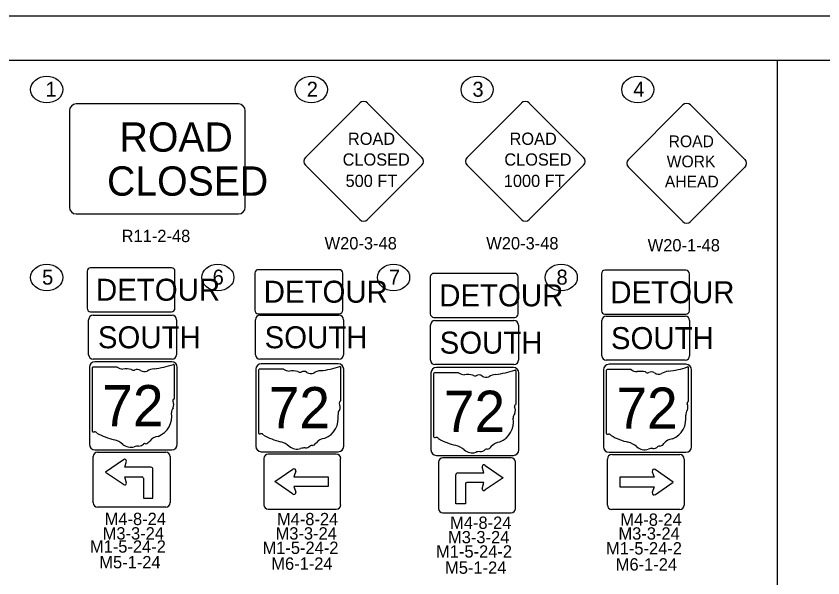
# Model space of a CAD drawing. Extents: x 0 to 784, y 0 to 440.
# Drawn here: x 466.8 to 650.3, y 312.3 to 440 of the extents above; entities that cross this region are included whole.
import ezdxf

# ---------------------------------------------------------------- set-up
doc = ezdxf.new("R2010")
doc.units = 0
for name, color, linetype in [('Default', 7, 'Continuous'), ('SH_Border', 7, 'Continuous'), ('SH_Cut_Line', 7, 'Continuous'), ('SN_P_Signs', 7, 'Continuous'), ('SN_P_Text', 7, 'Continuous'), ('SN_X_Public', 7, 'Continuous')]:
    doc.layers.add(name, color=color, linetype=linetype)

msp = doc.modelspace()

# ---------------------------------------------------------------- linework, layer by layer
at = {"layer": 'Default'}
for centre in [(473.78, 423.3), (533.97, 423.3), (571.68, 423.3), (608.24, 423.3), (473.78, 380.58), (512.71, 380.58), (552.68, 380.58), (590.82, 380.58)]:
    msp.add_ellipse(centre, major_axis=(3.66, 0), ratio=0.82844, dxfattribs=at)
at = {"layer": 'SH_Border'}
msp.add_line((640, 10), (640, 430), dxfattribs=at)
msp.add_lwpolyline([(30, 430), (670, 430), (670, 10), (30, 10)], close=True, dxfattribs=at)
at = {"layer": 'SH_Cut_Line'}
msp.add_lwpolyline([(0, 0), (680, 0), (680, 440), (0, 440)], close=True, dxfattribs=at)
at = {"layer": 'SN_P_Signs'}
for p, q in [((483.32, 362.99), (483.32, 370.99)), ((484.32, 371.99), (502.32, 371.99)), ((503.32, 370.99), (503.32, 362.99)), ((521.26, 362.99), (521.26, 370.99)), ((522.26, 371.99), (540.26, 371.99)), ((541.26, 370.99), (541.26, 362.99)), ((562.07, 370.77), (580.07, 370.77)), ((600.03, 362.8), (600.03, 370.8)), ((601.03, 371.8), (619.03, 371.8)), ((620.03, 370.8), (620.03, 362.8)), ((561.07, 361.77), (561.07, 369.77)), ((581.07, 369.77), (581.07, 361.77)), ((502.32, 361.99), (484.32, 361.99)), ((540.26, 361.99), (522.26, 361.99)), ((619.03, 361.8), (601.03, 361.8)), ((484.09, 359.97), (484.09, 345.74)), ((489.77, 360.22), (484.28, 360.22)), ((502.84, 353.13), (502.84, 360.57)), ((527.63, 359.77), (522.14, 359.77)), ((540.7, 352.68), (540.7, 360.13)), ((580.07, 360.77), (562.07, 360.77)), ((619.8, 352.56), (619.8, 360)), ((521.95, 359.53), (521.95, 345.3)), ((561.79, 358.7), (561.79, 344.47)), ((567.47, 358.94), (561.98, 358.94)), ((580.54, 351.85), (580.54, 359.29)), ((601.05, 359.4), (601.05, 345.17)), ((606.72, 359.65), (601.23, 359.65)), ((502.84, 353.13), (502.84, 353.13)), ((540.7, 352.68), (540.7, 352.68)), ((619.8, 352.56), (619.8, 352.56)), ((580.54, 351.85), (580.54, 351.85)), ((484.35, 329.38), (484.35, 339.88)), ((485.35, 340.88), (500.85, 340.88)), ((501.85, 339.88), (501.85, 329.38)), ((539.64, 340.43), (524.14, 340.43)), ((539.65, 340.43), (539.64, 340.43)), ((579.42, 339.6), (563.92, 339.6)), ((602.31, 340.31), (617.81, 340.31)), ((491.24, 339.15), (487.16, 336.35)), ((491.54, 337.45), (491.95, 338.85)), ((523.14, 339.43), (523.14, 328.93)), ((540.64, 328.93), (540.64, 339.43)), ((562.92, 338.6), (562.92, 328.1)), ((573.53, 337.86), (577.61, 335.07)), ((580.42, 328.1), (580.42, 338.6)), ((601.31, 328.81), (601.31, 339.31)), ((618.81, 339.31), (618.81, 328.81)), ((487.16, 336.35), (491.24, 333.56)), ((497.48, 337.45), (491.54, 337.45)), ((497.48, 337.45), (497.48, 337.45)), ((497.94, 330.41), (497.94, 336.98)), ((525.64, 334.18), (529.78, 337.03)), ((530.42, 336.56), (530.02, 335.28)), ((567.29, 336.16), (573.23, 336.16)), ((567.29, 336.16), (567.29, 336.16)), ((573.23, 336.16), (572.81, 337.57)), ((611.54, 336.43), (611.94, 335.15)), ((616.31, 334.06), (612.17, 336.9)), ((491.95, 333.85), (491.54, 335.26)), ((491.54, 335.26), (495.44, 335.26)), ((495.76, 334.95), (495.76, 330.41)), ((529.72, 331.39), (525.64, 334.18)), ((530.02, 335.28), (537.83, 335.28)), ((537.83, 335.28), (537.83, 333.09)), ((566.82, 329.13), (566.82, 335.69)), ((577.61, 335.07), (573.53, 332.27)), ((611.94, 335.15), (604.12, 335.15)), ((604.12, 335.15), (604.12, 332.96)), ((612.23, 331.26), (616.31, 334.06)), ((537.83, 333.09), (530.02, 333.09)), ((530.02, 333.09), (530.42, 331.81)), ((569.01, 333.66), (569.01, 329.13)), ((573.23, 333.97), (569.32, 333.97)), ((572.81, 332.57), (573.23, 333.97)), ((604.12, 332.96), (611.94, 332.96)), ((611.94, 332.96), (611.54, 331.68)), ((495.76, 330.41), (497.94, 330.41)), ((495.76, 330.41), (497.94, 330.41)), ((569.01, 329.13), (566.82, 329.13)), ((500.85, 328.38), (485.35, 328.38)), ((524.14, 327.93), (539.64, 327.93)), ((563.92, 327.1), (579.42, 327.1)), ((617.81, 327.81), (602.31, 327.81))]:
    msp.add_line(p, q, dxfattribs=at)
for points in [[(532.61, 407.88), (544.99, 420.25)], [(546.75, 420.25), (559.13, 407.88)], [(569.39, 407.88), (581.76, 420.25)], [(583.53, 420.25), (595.91, 407.88)], [(478.94, 418.46), (478.94, 396.6)], [(517.37, 420.03), (480.5, 420.03)], [(518.94, 396.6), (518.94, 418.46)], [(606.11, 407.43), (618.48, 419.8)], [(620.25, 419.8), (632.62, 407.43)], [(544.99, 393.73), (532.61, 406.11)], [(559.13, 406.11), (546.75, 393.73)], [(581.76, 393.73), (569.39, 406.11)], [(595.91, 406.11), (583.53, 393.73)], [(618.48, 393.28), (606.11, 405.66)], [(632.62, 405.66), (620.25, 393.28)], [(480.5, 395.03), (517.37, 395.03)], [(482.96, 382), (482.96, 373.6)], [(502.16, 382.8), (483.76, 382.8)], [(502.96, 373.6), (502.96, 382)], [(483.76, 372.8), (502.16, 372.8)], [(483.48, 360.16), (483.48, 342.66)], [(502.23, 361.41), (484.73, 361.41)], [(503.48, 342.66), (503.48, 360.16)], [(521.34, 359.72), (521.34, 342.22)], [(540.09, 360.97), (522.59, 360.97)], [(541.34, 342.22), (541.34, 359.72)], [(579.93, 360.14), (562.43, 360.14)], [(619.19, 360.84), (601.69, 360.84)], [(561.18, 358.89), (561.18, 341.39)], [(581.18, 341.39), (581.18, 358.89)], [(600.44, 359.59), (600.44, 342.09)], [(620.44, 342.09), (620.44, 359.59)], [(484.73, 341.41), (502.23, 341.41)], [(522.59, 340.97), (540.09, 340.97)], [(562.43, 340.14), (579.93, 340.14)], [(601.69, 340.84), (619.19, 340.84)]]:
    msp.add_lwpolyline(points, dxfattribs=at)
for centre, radius, start, end in [((545.87, 419.37), 1.25, 45, 135), ((582.65, 419.37), 1.25, 45, 135), ((480.5, 418.46), 1.57, 90, 180), ((517.37, 418.46), 1.57, 0, 90), ((619.36, 418.92), 1.25, 45, 135), ((533.5, 406.99), 1.25, 135, 225), ((558.24, 406.99), 1.25, 315, 45), ((570.27, 406.99), 1.25, 135, 225), ((595.02, 406.99), 1.25, 315, 45), ((606.99, 406.54), 1.25, 135, 225), ((631.74, 406.54), 1.25, 315, 45), ((480.5, 396.6), 1.57, 180, 270), ((517.37, 396.6), 1.57, 270, 0), ((545.87, 394.62), 1.25, 225, 315), ((582.65, 394.62), 1.25, 225, 315), ((619.36, 394.17), 1.25, 225, 315), ((483.76, 382), 0.8, 90, 180), ((502.16, 382), 0.8, 0, 90), ((483.76, 373.6), 0.8, 180, 270), ((502.16, 373.6), 0.8, 270, 0), ((484.32, 370.99), 1, 90, 180), ((502.32, 370.99), 1, 0, 90), ((522.26, 370.99), 1, 90, 180), ((540.26, 370.99), 1, 0, 90), ((562.07, 369.77), 1, 90, 180), ((580.07, 369.77), 1, 0, 90), ((601.03, 370.79), 1, 90, 180), ((619.03, 370.79), 1, 0, 90), ((484.32, 362.99), 1, 180, 270), ((502.32, 362.99), 1, 270, 0), ((522.26, 362.99), 1, 180, 270), ((540.26, 362.99), 1, 270, 0), ((562.07, 361.77), 1, 180, 270), ((580.07, 361.77), 1, 270, 0), ((601.03, 362.79), 1, 180, 270), ((619.03, 362.79), 1, 270, 0), ((484.73, 360.16), 1.25, 90, 180), ((484.31, 360), 0.217, 98.1301, 188.1301), ((491.08, 361.87), 2.11, 231.6195, 271.1119), ((491.78, 352.23), 7.56, 80.4867, 94.9883), ((493.49, 360.08), 0.608, 219.7921, 297.1024), ((494.38, 358.43), 1.26, 54.4667, 119.1411), ((498.7, 355.87), 4, 97.3462, 120.7689), ((496.16, 379.62), 19.88, 275.8445, 288.9065), ((502.23, 360.16), 1.25, 0, 90), ((502.63, 360.6), 0.209, 351.8621, 97.738), ((522.59, 359.72), 1.25, 90, 180), ((522.17, 359.56), 0.217, 98.1301, 188.1301), ((528.94, 361.43), 2.11, 231.6195, 271.1119), ((534.02, 379.18), 19.88, 275.8445, 288.9065), ((540.09, 359.72), 1.25, 0, 90), ((540.49, 360.16), 0.209, 351.8621, 97.738), ((562.43, 358.89), 1.25, 90, 180), ((579.93, 358.89), 1.25, 0, 90), ((601.69, 359.59), 1.25, 90, 180), ((613.12, 379.05), 19.88, 275.8445, 288.9065), ((619.19, 359.59), 1.25, 0, 90), ((619.59, 360.03), 0.209, 351.8621, 97.738), ((496.02, 360.69), 1.52, 233.8562, 294.8282), ((529.63, 351.78), 7.56, 80.4867, 94.9883), ((531.35, 359.63), 0.608, 219.7921, 297.1024), ((532.24, 357.99), 1.26, 54.4667, 119.1411), ((533.88, 360.24), 1.52, 233.8562, 294.8282), ((536.56, 355.43), 4, 97.3462, 120.7689), ((562.01, 358.73), 0.217, 98.1301, 188.1301), ((568.77, 360.59), 2.11, 231.6195, 271.1119), ((569.47, 350.95), 7.56, 80.4867, 94.9883), ((571.19, 358.8), 0.608, 219.7921, 297.1024), ((572.08, 357.16), 1.26, 54.4667, 119.1411), ((573.71, 359.41), 1.52, 233.8562, 294.8282), ((576.4, 354.59), 4, 97.3462, 120.7689), ((573.86, 378.34), 19.88, 275.8445, 288.9065), ((580.33, 359.32), 0.209, 351.8621, 97.738), ((601.26, 359.43), 0.217, 98.1301, 188.1301), ((608.03, 361.3), 2.11, 231.6195, 271.1119), ((608.73, 351.66), 7.56, 80.4867, 94.9883), ((610.45, 359.51), 0.608, 219.7921, 297.1024), ((611.34, 357.86), 1.26, 54.4667, 119.1411), ((612.97, 360.12), 1.52, 233.8562, 294.8282), ((615.66, 355.3), 4, 97.3462, 120.7689), ((502.79, 352.58), 0.323, 107.944, 210.337), ((500.74, 351.64), 1.94, 340.033, 23.6496), ((502.62, 353.1), 0.223, 289.6038, 7.7341), ((540.65, 352.14), 0.323, 107.944, 210.337), ((540.48, 352.65), 0.223, 289.6038, 7.7341), ((619.58, 352.53), 0.223, 289.6038, 7.7341), ((503.59, 350.01), 1.41, 136.8065, 186.9296), ((541.45, 349.57), 1.41, 136.8065, 186.9296), ((538.6, 351.19), 1.94, 340.033, 23.6496), ((580.49, 351.3), 0.323, 107.944, 210.337), ((578.44, 350.36), 1.94, 340.033, 23.6496), ((580.32, 351.82), 0.223, 289.6038, 7.7341), ((619.75, 352.01), 0.323, 107.944, 210.337), ((617.7, 351.07), 1.94, 340.033, 23.6496), ((497.28, 349.06), 4.97, 292.3089, 8.9858), ((535.14, 348.62), 4.97, 292.3089, 8.9858), ((581.29, 348.73), 1.41, 136.8065, 186.9296), ((614.23, 348.49), 4.97, 292.3089, 8.9858), ((620.55, 349.44), 1.41, 136.8065, 186.9296), ((574.98, 347.79), 4.97, 292.3089, 8.9858), ((484.31, 345.71), 0.219, 171.9584, 258.3066), ((484.34, 347.17), 1.67, 267.339, 280.6039), ((484.69, 344.92), 0.603, 29.7484, 93.2717), ((492.3, 357.71), 14.36, 240.4129, 257.1985), ((522.17, 345.27), 0.219, 171.9584, 258.3066), ((522.2, 346.72), 1.67, 267.339, 280.6039), ((522.55, 344.48), 0.603, 29.7484, 93.2717), ((601.27, 345.14), 0.219, 171.9584, 258.3066), ((488.02, 339.35), 4.49, 47.1842, 75.836), ((495.92, 344.36), 1.61, 282.8732, 323.2771), ((499.37, 341.75), 2.72, 94.4031, 142.5768), ((530.16, 357.26), 14.36, 240.4129, 257.1985), ((525.88, 338.9), 4.49, 47.1842, 75.836), ((537.23, 341.3), 2.72, 94.4031, 142.5768), ((562.01, 344.43), 0.219, 171.9584, 258.3066), ((562.04, 345.89), 1.67, 267.339, 280.6039), ((562.38, 343.64), 0.603, 29.7484, 93.2717), ((570, 356.43), 14.36, 240.4129, 257.1985), ((577.07, 340.47), 2.72, 94.4031, 142.5768), ((601.3, 346.6), 1.67, 267.339, 280.6039), ((601.64, 344.35), 0.603, 29.7484, 93.2717), ((609.25, 357.14), 14.36, 240.4129, 257.1985), ((616.33, 341.18), 2.72, 94.4031, 142.5768), ((484.73, 342.66), 1.25, 180, 270), ((492.88, 344.85), 2.85, 230.7004, 286.2918), ((494.52, 339.93), 2.34, 85.6951, 111.2099), ((494.73, 343.79), 1.52, 268.777, 315.5493), ((496.11, 342.41), 0.428, 65.7517, 132.6484), ((502.23, 342.66), 1.25, 270, 0), ((522.59, 342.22), 1.25, 180, 270), ((530.74, 344.41), 2.85, 230.7004, 286.2918), ((532.38, 339.49), 2.34, 85.6951, 111.2099), ((532.59, 343.34), 1.52, 268.777, 315.5493), ((533.97, 341.96), 0.428, 65.7517, 132.6484), ((533.78, 343.92), 1.61, 282.8732, 323.2771), ((540.09, 342.22), 1.25, 270, 0), ((562.43, 341.39), 1.25, 180, 270), ((565.72, 338.07), 4.49, 47.1842, 75.836), ((570.58, 343.57), 2.85, 230.7004, 286.2918), ((572.43, 342.51), 1.52, 268.777, 315.5493), ((573.8, 341.13), 0.428, 65.7517, 132.6484), ((573.62, 343.09), 1.61, 282.8732, 323.2771), ((579.93, 341.39), 1.25, 270, 0), ((601.69, 342.09), 1.25, 180, 270), ((604.97, 338.78), 4.49, 47.1842, 75.836), ((609.83, 344.28), 2.85, 230.7004, 286.2918), ((611.48, 339.36), 2.34, 85.6951, 111.2099), ((611.69, 343.22), 1.52, 268.777, 315.5493), ((613.06, 341.84), 0.428, 65.7517, 132.6484), ((612.88, 343.79), 1.61, 282.8732, 323.2771), ((619.19, 342.09), 1.25, 270, 0), ((485.35, 339.89), 1, 90, 180), ((500.85, 339.89), 1, 0, 90), ((524.15, 339.43), 1, 90, 180), ((539.65, 339.43), 1, 0, 90), ((563.92, 338.6), 1, 90, 180), ((572.22, 338.65), 2.34, 85.6951, 111.2099), ((579.42, 338.6), 1, 0, 90), ((602.31, 339.31), 1, 90, 180), ((617.81, 339.31), 1, 0, 90), ((491.54, 338.85), 0.417, 0.0017, 134.9999), ((573.23, 337.57), 0.417, 45.0001, 179.9983), ((497.48, 336.98), 0.469, 0, 90), ((530.02, 336.68), 0.417, 342.7954, 124.5888), ((567.29, 335.69), 0.469, 90, 180), ((611.94, 336.56), 0.417, 55.4112, 197.2046), ((495.44, 334.95), 0.312, 0, 90), ((491.54, 333.85), 0.417, 225.0001, 0.0017), ((569.32, 333.66), 0.312, 90, 180), ((573.23, 332.57), 0.417, 179.9983, 314.9999), ((530.02, 331.68), 0.417, 224.9904, 17.2046), ((611.94, 331.56), 0.417, 162.7954, 315.0096), ((485.35, 329.39), 1, 180, 270), ((500.85, 329.39), 1, 270, 360), ((524.15, 328.93), 1, 180, 270), ((539.65, 328.93), 1, 270, 0), ((602.31, 328.81), 1, 180, 270), ((617.81, 328.81), 1, 270, 360), ((563.92, 328.1), 1, 180, 270), ((579.42, 328.1), 1, 270, 0)]:
    msp.add_arc(centre, radius, start, end, dxfattribs=at)
at = {"layer": 'SN_X_Public'}
for points in [[(540.32, 382.35), (521.92, 382.35)], [(619.16, 382.23), (600.76, 382.23)], [(521.12, 381.55), (521.12, 373.15)], [(541.12, 373.15), (541.12, 381.55)], [(561.04, 380.72), (561.04, 372.32)], [(580.24, 381.52), (561.84, 381.52)], [(581.04, 372.32), (581.04, 380.72)], [(599.96, 381.43), (599.96, 373.03)], [(619.96, 373.03), (619.96, 381.43)], [(521.92, 372.35), (540.32, 372.35)], [(561.84, 371.52), (580.24, 371.52)], [(600.76, 372.23), (619.16, 372.23)]]:
    msp.add_lwpolyline(points, dxfattribs=at)
for centre, start, end in [((521.92, 381.55), 90, 180), ((540.32, 381.55), 0, 90), ((600.76, 381.43), 90, 180), ((619.16, 381.43), 0, 90), ((561.84, 380.72), 90, 180), ((580.24, 380.72), 0, 90), ((521.92, 373.15), 180, 270), ((540.32, 373.15), 270, 0), ((600.76, 373.03), 180, 270), ((619.16, 373.03), 270, 0), ((561.84, 372.32), 180, 270), ((580.24, 372.32), 270, 0)]:
    msp.add_arc(centre, 0.8, start, end, dxfattribs=at)

# ---------------------------------------------------------------- texts
at = {"layer": 'Default'}
for s, p in [('1', (473.5, 421.68)), ('2', (532.93, 421.68)), ('3', (570.62, 421.68)), ('4', (607.2, 421.68)), ('5', (472.73, 378.96)), ('6', (511.52, 378.96)), ('7', (551.63, 378.96)), ('8', (589.75, 378.96))]:
    msp.add_text(s, height=3.41, dxfattribs=at).set_placement(p)
at = {"layer": 'SN_P_Signs'}
for s, height, p in [('ROAD', 6.667, (490.36, 409.18)), ('ROAD', 2.778, (542.3, 410.74)), ('ROAD', 2.778, (579.07, 410.74)), ('ROAD', 2.665, (615.25, 410.21)), ('CLOSED', 2.778, (541.1, 406.02)), ('CLOSED', 2.778, (577.88, 406.02)), ('WORK', 2.665, (614.81, 405.63)), ('CLOSED', 6.667, (487.5, 399.18)), ('500 FT', 2.778, (541.76, 401.16)), ('1000 FT', 2.778, (577.76, 401.16)), ('AHEAD', 2.665, (614.38, 401.05)), ('DETOUR', 5, (484.99, 375.3)), ('SOUTH', 5, (485.41, 364.49)), ('SOUTH', 5, (523.34, 364.49)), ('SOUTH', 5, (602.12, 364.3)), ('SOUTH', 5, (563.16, 363.27)), ('72', 9.375, (486.41, 346.75)), ('72', 9.375, (524.27, 346.3)), ('72', 9.375, (564.11, 345.47)), ('72', 9.375, (603.36, 346.18))]:
    msp.add_text(s, height=height, dxfattribs=at).set_placement(p)
at = {"layer": 'SN_P_Text'}
for s, p in [('R11-2-48', (490.82, 388.63)), ('W20-3-48', (536.99, 386.97)), ('W20-3-48', (573.76, 386.97)), ('W20-1-48', (610.48, 386.52)), ('M4-8-24', (486.96, 324.3)), ('M4-8-24', (526.15, 324.26)), ('M4-8-24', (604.28, 324.13)), ('M4-8-24', (565.54, 323.43)), ('M3-3-24', (486.51, 321.01)), ('M3-3-24', (525.84, 321.01)), ('M3-3-24', (565.07, 320.15)), ('M3-3-24', (603.84, 320.99)), ('M1-5-24-2', (483.61, 318.02)), ('M1-5-24-2', (522.87, 317.74)), ('M1-5-24-2', (562.35, 316.9)), ('M1-5-24-2', (601, 317.61)), ('M5-1-24', (485.74, 314.47)), ('M6-1-24', (524.86, 314.14)), ('M5-1-24', (564.4, 313.22)), ('M6-1-24', (603.22, 313.96))]:
    msp.add_text(s, height=2.8, dxfattribs=at).set_placement(p)
at = {"layer": 'SN_X_Public'}
for p in [(523.15, 374.85), (563.07, 374.02), (601.99, 374.73)]:
    msp.add_text('DETOUR', height=5, dxfattribs=at).set_placement(p)

doc.saveas('drawing.dxf')
